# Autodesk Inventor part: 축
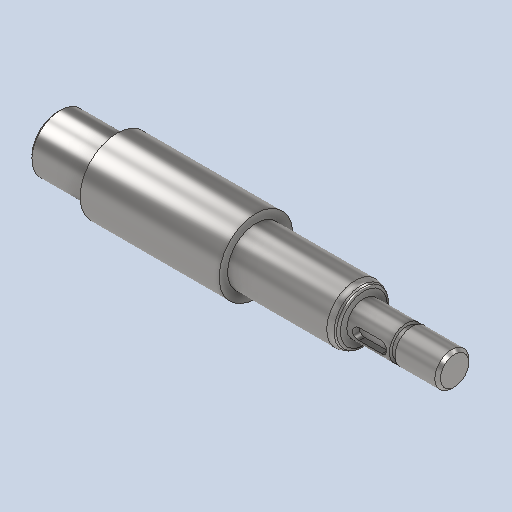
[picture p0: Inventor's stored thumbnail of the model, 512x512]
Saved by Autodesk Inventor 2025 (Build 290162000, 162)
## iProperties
Created: 2024-08
Part Number: 축
Material: 강철, 연강
Document SubType Name: Modeling
Designer: SAMSUNG
Density: 7.86 g/cm^3
Appearance: 기본값
Author: jhkim
Sending System: Autodesk Inventor 2025
Preprocessor: ST-DEVELOPER v20
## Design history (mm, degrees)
feature "솔리드2"
node "솔리드1"
